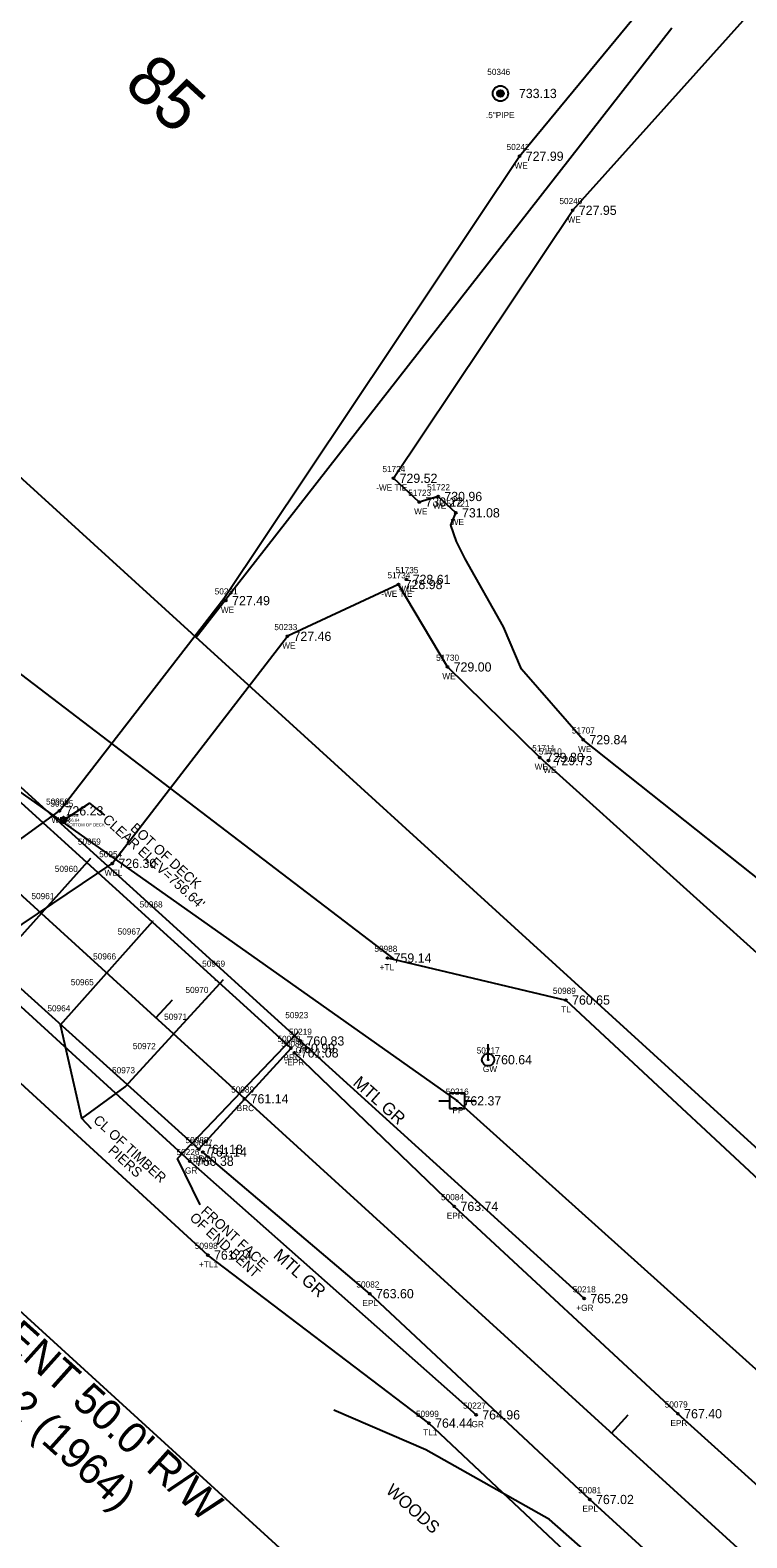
# Model space of a CAD drawing. Extents: x 1378245 to 1381654, y 996521 to 1000567.
# Drawn here: x 1379687.6 to 1379803.9, y 998853.4 to 999097.9 of the extents above; entities that cross this region are included whole.
import ezdxf

# ---------------------------------------------------------------- set-up
doc = ezdxf.new("R2010")
doc.units = 0
for name, color, linetype in [('Default', 7, 'Continuous'), ('RD_EX_Bridge', 7, 'Continuous'), ('RD_EX_Bridge_txCode', 7, 'Continuous'), ('RD_EX_DV_Prop', 7, 'Continuous'), ('RD_EX_DV_Prop_txCode', 7, 'Continuous'), ('RD_EX_DV_PropPin', 7, 'Continuous'), ('RD_EX_GuardRail', 7, 'Continuous'), ('RD_EX_GuardRail_txCode', 7, 'Continuous'), ('RD_EX_H2O', 7, 'Continuous'), ('RD_EX_H2O_txCode', 7, 'Continuous'), ('RD_EX_Road', 7, 'Continuous'), ('RD_EX_Road_txCode', 7, 'Continuous'), ('RD_EX_RW', 7, 'Continuous'), ('RD_EX_RW_TX', 7, 'Continuous'), ('RD_EX_SU_Elec', 7, 'Continuous'), ('RD_EX_TX_Bridge_ELEV', 7, 'Continuous'), ('RD_EX_TX_DV_Prop_ELEV', 7, 'Continuous'), ('RD_EX_TX_GuardRail_ELEV', 7, 'Continuous'), ('RD_EX_TX_H2O_ELEV', 7, 'Continuous'), ('RD_EX_TX_Road_ELEV', 7, 'Continuous'), ('RD_EX_TX_UT_ELEV', 7, 'Continuous'), ('RD_EX_TX_VEG_ELEV', 7, 'Continuous'), ('RD_EX_UT', 7, 'Continuous'), ('RD_EX_UT_txCode', 7, 'Continuous'), ('RD_EX_VEG', 7, 'Continuous'), ('RD_EX_VEG_txCode', 7, 'Continuous'), ('RD_HC_Cl', 7, 'Continuous'), ('RD_HC_Data_Tic', 7, 'Continuous'), ('RD_HC_Survey_ELEV', 7, 'Continuous'), ('RD_HC_TX_Sta50', 7, 'Continuous'), ('RD_SMD_Locator', 7, 'Continuous'), ('RD_TX_Misc1', 7, 'Continuous'), ('RD_TX_Misc2', 7, 'Continuous')]:
    doc.layers.add(name, color=color, linetype=linetype)

msp = doc.modelspace()

# ---------------------------------------------------------------- linework, layer by layer
at = {"layer": 'Default'}
for p, q in [((1379693.05, 998969.77), (1379693.03, 998969.77)), ((1379693.04, 998969.78), (1379693.04, 998969.76)), ((1379697.51, 998963.6), (1379697.49, 998963.6)), ((1379697.5, 998963.61), (1379697.5, 998963.59)), ((1379693.83, 998959.18), (1379693.81, 998959.18)), ((1379693.82, 998959.19), (1379693.82, 998959.17)), ((1379689.7, 998954.76), (1379689.7, 998954.75)), ((1379689.71, 998954.76), (1379689.7, 998954.76)), ((1379707.56, 998953.42), (1379707.55, 998953.42)), ((1379707.56, 998953.43), (1379707.56, 998953.42)), ((1379703.98, 998949.01), (1379703.96, 998949.01)), ((1379703.97, 998949.02), (1379703.97, 998949)), ((1379700.03, 998944.98), (1379700.01, 998944.98)), ((1379700.02, 998944.99), (1379700.02, 998944.97)), ((1379717.7, 998943.8), (1379717.68, 998943.8)), ((1379717.69, 998943.81), (1379717.69, 998943.79)), ((1379696.39, 998940.8), (1379696.37, 998940.8)), ((1379696.38, 998940.81), (1379696.38, 998940.79)), ((1379715.01, 998939.54), (1379714.99, 998939.54)), ((1379715, 998939.55), (1379715, 998939.53)), ((1379692.59, 998936.56), (1379692.57, 998936.56)), ((1379692.58, 998936.57), (1379692.58, 998936.55)), ((1379711.22, 998935.19), (1379711.2, 998935.19)), ((1379711.21, 998935.2), (1379711.21, 998935.18)), ((1379731.16, 998935.46), (1379731.14, 998935.46)), ((1379731.15, 998935.46), (1379731.15, 998935.45)), ((1379706.43, 998930.43), (1379706.41, 998930.43)), ((1379706.42, 998930.44), (1379706.42, 998930.43)), ((1379703.04, 998926.52), (1379703.04, 998926.5)), ((1379703.05, 998926.51), (1379703.04, 998926.51))]:
    msp.add_line(p, q, dxfattribs=at)
msp.add_lwpolyline([(1379692.44, 998969.77), (1379693.64, 998969.77), (1379693.04, 998969.77), (1379693.04, 998970.37), (1379693.04, 998969.17)], dxfattribs=at)
msp.add_circle((1379693.04, 998969.77), 0.469, dxfattribs=at)
at = {"layer": 'RD_EX_Bridge'}
for p, q in [((1379681.87, 998946.21), (1379697.5, 998963.6)), ((1379692.58, 998936.56), (1379707.56, 998953.42)), ((1379703.04, 998926.51), (1379719.03, 998943.94)), ((1379711.57, 998914.92), (1379731.15, 998935.46))]:
    msp.add_line(p, q, dxfattribs=at)
msp.add_lwpolyline([(1379715.01, 998916.39), (1379729.96, 998932.8), (1379652.41, 999003.17), (1379637.22, 998986.55), (1379715.01, 998916.39)], dxfattribs=at)
at = {"layer": 'RD_EX_DV_Prop'}
msp.add_line((1379791.75, 999098.24), (1379714.55, 998999.4), dxfattribs=at)
at = {"layer": 'RD_EX_DV_PropPin'}
for p, q in [((1379763.42, 999087.51), (1379763.42, 999087.79)), ((1379763.44, 999087.44), (1379763.44, 999087.86)), ((1379763.47, 999087.38), (1379763.47, 999087.91)), ((1379763.49, 999087.34), (1379763.49, 999087.95)), ((1379763.52, 999087.31), (1379763.52, 999087.99)), ((1379763.54, 999087.28), (1379763.54, 999088.02)), ((1379763.57, 999087.25), (1379763.57, 999088.04)), ((1379763.59, 999087.23), (1379763.59, 999088.06)), ((1379763.62, 999087.21), (1379763.62, 999088.08)), ((1379763.64, 999087.19), (1379763.64, 999088.1)), ((1379763.67, 999087.18), (1379763.67, 999088.12)), ((1379763.69, 999087.17), (1379763.69, 999088.13)), ((1379763.72, 999087.15), (1379763.72, 999088.14)), ((1379763.74, 999087.14), (1379763.74, 999088.15)), ((1379763.77, 999087.13), (1379763.77, 999088.16)), ((1379763.79, 999087.13), (1379763.79, 999088.17)), ((1379763.82, 999087.12), (1379763.82, 999088.18)), ((1379763.84, 999087.11), (1379763.84, 999088.18)), ((1379763.87, 999087.11), (1379763.87, 999088.19)), ((1379763.89, 999087.11), (1379763.89, 999088.19)), ((1379763.92, 999087.11), (1379763.92, 999088.19)), ((1379763.94, 999087.1), (1379763.94, 999088.19)), ((1379763.97, 999087.11), (1379763.97, 999088.19)), ((1379763.99, 999087.11), (1379763.99, 999088.19)), ((1379764.02, 999087.11), (1379764.02, 999088.19)), ((1379764.04, 999087.11), (1379764.04, 999088.18)), ((1379764.07, 999087.12), (1379764.07, 999088.18)), ((1379764.09, 999087.13), (1379764.09, 999088.17)), ((1379764.12, 999087.13), (1379764.12, 999088.16)), ((1379764.14, 999087.14), (1379764.14, 999088.15)), ((1379764.17, 999087.15), (1379764.17, 999088.14)), ((1379764.19, 999087.17), (1379764.19, 999088.13)), ((1379764.22, 999087.18), (1379764.22, 999088.12)), ((1379764.24, 999087.19), (1379764.24, 999088.1)), ((1379764.27, 999087.21), (1379764.27, 999088.08)), ((1379764.29, 999087.23), (1379764.29, 999088.06)), ((1379764.32, 999087.25), (1379764.32, 999088.04)), ((1379764.34, 999087.28), (1379764.34, 999088.02)), ((1379764.37, 999087.31), (1379764.37, 999087.99)), ((1379764.39, 999087.34), (1379764.39, 999087.95)), ((1379764.42, 999087.38), (1379764.42, 999087.91)), ((1379764.44, 999087.44), (1379764.44, 999087.86)), ((1379764.47, 999087.51), (1379764.47, 999087.79))]:
    msp.add_line(p, q, dxfattribs=at)
for radius in [1.25, 0.543]:
    msp.add_circle((1379763.94, 999087.65), radius, dxfattribs=at)
at = {"layer": 'RD_EX_GuardRail'}
for points in [[(1379497.52, 999109.58), (1379635.64, 998985.68), (1379713.53, 998914.45), (1379759.99, 998873.32)], [(1379777.52, 998892.18), (1379731.47, 998933.97), (1379653.8, 999004.42), (1379553.93, 999097.04)]]:
    msp.add_lwpolyline(points, dxfattribs=at)
at = {"layer": 'RD_EX_H2O'}
for points in [[(1379663.75, 998950.52), (1379692.38, 998971.29), (1379719.04, 999005.74), (1379767.05, 999077.47), (1379820.32, 999142.06), (1379856.78, 999184.17), (1379909.65, 999199.37), (1379968.41, 999216.31), (1380029.43, 999227.41), (1380049.41, 999276.13), (1380067, 999316.44)], [(1379746.58, 999025.23), (1379775.66, 999068.7), (1379833.36, 999132.97), (1379865.6, 999174.54), (1379921.65, 999184.16), (1379977.93, 999198.09), (1380034.4, 999218.74), (1380062.36, 999262.9), (1380081.88, 999311.7)], [(1379756.7, 999019.63), (1379753.84, 999022.28), (1379750.77, 999021.38), (1379746.58, 999025.23)], [(1379918.79, 998846.24), (1379910.28, 998856.59), (1379904.93, 998863.62), (1379897.77, 998868.2), (1379895.82, 998874.91), (1379890.92, 998880.91), (1379881.01, 998897.71), (1379867.05, 998914.16), (1379841.93, 998934), (1379817.55, 998950.92), (1379777.38, 998982.83), (1379767.36, 998994.27), (1379764.43, 999001.11), (1379758.21, 999012.18), (1379756.79, 999014.96), (1379755.88, 999017.65), (1379756.7, 999019.63)], [(1379901.08, 998848.93), (1379897.44, 998858.7), (1379895.56, 998859.46), (1379891.1, 998862.46), (1379885.95, 998867.36), (1379882.04, 998876.42), (1379877.1, 998894.85), (1379861.31, 998910.26), (1379835.53, 998927.59), (1379812.63, 998941.87), (1379770.33, 998979.95), (1379755.35, 998994.63), (1379747.4, 999008), (1379729.37, 998999.6)], [(1379671.83, 998943.2), (1379700.96, 998962.76), (1379729.37, 998999.6)], [(1380261.25, 998409.34), (1380207.72, 998459.99), (1380160.95, 998503.9), (1380116.04, 998544.61), (1380073.47, 998582.91), (1380032.2, 998621.67), (1379983.75, 998664.27), (1379936.35, 998705.94), (1379893.4, 998746.57), (1379847.09, 998789.13), (1379801.41, 998830.34), (1379771.89, 998856.37), (1379751.83, 998867.64), (1379736.89, 998874.07)]]:
    msp.add_lwpolyline(points, dxfattribs=at)
at = {"layer": 'RD_EX_Road'}
for points in [[(1380011.64, 998674.46), (1379968.26, 998714.25), (1379924.81, 998753.18), (1379879.74, 998794.22), (1379836.83, 998833.73), (1379792.75, 998873.5), (1379756.46, 998907.13), (1379730.54, 998932.03)], [(1379997.47, 998660), (1379953.44, 998699.92), (1379910.65, 998738.56), (1379864.96, 998780.17), (1379823.13, 998818.8), (1379778.45, 998859.59), (1379742.74, 998892.97), (1379715.65, 998915.95)]]:
    msp.add_lwpolyline(points, dxfattribs=at)
at = {"layer": 'RD_EX_RW'}
for p, q in [((1379446.02, 999244.05), (1379815.63, 998907.31)), ((1379378.68, 999170.13), (1379748.28, 998833.39))]:
    msp.add_line(p, q, dxfattribs=at)
at = {"layer": 'RD_EX_SU_Elec'}
msp.add_lwpolyline([(1378514.25, 999944.12), (1378777.7, 999831.22), (1379190.17, 999461.05), (1379403.33, 999174.04), (1379756.94, 998924.25), (1380051.16, 998659.97), (1380327.91, 998390.65), (1380546.23, 998058.37)], dxfattribs=at)
at = {"layer": 'RD_EX_UT'}
for p, q in [((1379761.93, 998930.92), (1379761.93, 998933.42)), ((1379758.18, 998925.51), (1379755.68, 998925.51)), ((1379755.68, 998925.51), (1379755.68, 998923.01)), ((1379758.18, 998923.01), (1379758.18, 998925.51)), ((1379753.97, 998924.23), (1379755.7, 998924.23)), ((1379755.68, 998923.01), (1379758.18, 998923.01)), ((1379758.15, 998924.23), (1379759.97, 998924.23))]:
    msp.add_line(p, q, dxfattribs=at)
msp.add_circle((1379761.93, 998930.92), 1, dxfattribs=at)
at = {"layer": 'RD_EX_VEG'}
for p, q in [((1379635.72, 999031.86), (1379746.57, 998947.26)), ((1379716.47, 998899.23), (1379620.44, 998987.26))]:
    msp.add_line(p, q, dxfattribs=at)
for points in [[(1379745.61, 998947.42), (1379774.57, 998940.6), (1379816.01, 998901.98), (1379842.25, 998875.07), (1379890.91, 998833.28), (1379928.8, 998787.62), (1379978.22, 998752.26), (1380041.75, 998705.92), (1380067.2, 998663.35), (1380118.8, 998637.22), (1380159.3, 998606.26), (1380204.39, 998555.8), (1380215.44, 998549.46)], [(1380572.26, 997755.47), (1380563.06, 997802.88), (1380548.57, 997859.96), (1380528.6, 997926.15), (1380512.76, 997988.52), (1380488.02, 998054.97), (1380458.55, 998120.18), (1380432.73, 998176.36), (1380395.75, 998235.49), (1380345.67, 998286.69), (1380306.05, 998354.38), (1380256.57, 998407.41), (1380203.97, 998456.66), (1380158.7, 998500.55), (1380112.46, 998542.96), (1380070.42, 998580.38), (1380028.44, 998619.77), (1379982.76, 998660.07), (1379934.04, 998703.39), (1379891.18, 998743.94), (1379841.91, 998788.98), (1379798.41, 998828.62), (1379752.34, 998871.98), (1379716.47, 998899.23)]]:
    msp.add_lwpolyline(points, dxfattribs=at)
at = {"layer": 'RD_HC_Cl'}
msp.add_line((1378781.54, 999781.8), (1380217.09, 998473.92), dxfattribs=at)
at = {"layer": 'RD_HC_Data_Tic'}
for p, q in [((1379708.03, 998937.7), (1379710.73, 998940.66)), ((1379781.96, 998870.35), (1379784.65, 998873.31))]:
    msp.add_line(p, q, dxfattribs=at)
at = {"layer": 'RD_SMD_Locator'}
for centre, radius in [((1379763.94, 999087.65), 0.075), ((1379767.05, 999077.47), 0.15), ((1379775.66, 999068.7), 0.15), ((1379746.58, 999025.23), 0.15), ((1379750.77, 999021.38), 0.15), ((1379753.84, 999022.28), 0.15), ((1379756.7, 999019.63), 0.15), ((1379747.4, 999008), 0.15), ((1379748.7, 999008.83), 0.15), ((1379719.41, 999005.39), 0.15), ((1379729.37, 998999.6), 0.15), ((1379755.35, 998994.63), 0.15), ((1379777.38, 998982.83), 0.15), ((1379770.33, 998979.95), 0.15), ((1379771.73, 998979.43), 0.15), ((1379692.38, 998971.29), 0.15), ((1379700.96, 998962.76), 0.15), ((1379745.61, 998947.42), 0.15), ((1379774.57, 998940.6), 0.15), ((1379729.96, 998932.8), 0.15), ((1379730.54, 998932.03), 0.15), ((1379731.47, 998933.97), 0.15), ((1379761.93, 998930.92), 0.075), ((1379722.41, 998924.58), 0.15), ((1379756.94, 998924.25), 0.075), ((1379715.01, 998916.39), 0.15), ((1379715.65, 998915.95), 0.15), ((1379713.53, 998914.45), 0.15), ((1379756.46, 998907.13), 0.15), ((1379716.47, 998899.23), 0.15), ((1379742.74, 998892.97), 0.15), ((1379777.52, 998892.18), 0.15), ((1379759.99, 998873.32), 0.15), ((1379792.75, 998873.5), 0.15), ((1379752.34, 998871.98), 0.15), ((1379778.45, 998859.59), 0.15)]:
    msp.add_circle(centre, radius, dxfattribs=at)
at = {"layer": 'RD_TX_Misc1'}
for p, q in [((1379696.04, 998921.41), (1379692.58, 998936.56)), ((1379715.22, 998907.36), (1379711.57, 998914.92))]:
    msp.add_line(p, q, dxfattribs=at)
msp.add_lwpolyline([(1379693.04, 998969.77), (1379697.26, 998972.56), (1379699.72, 998970.59)], dxfattribs=at)
msp.add_circle((1379693.04, 998969.77), 0.466, dxfattribs=at)
at = {"layer": 'RD_TX_Misc2'}
msp.add_lwpolyline([(1379697.61, 998919.72), (1379696.04, 998921.41), (1379703.04, 998926.51)], dxfattribs=at)

# ---------------------------------------------------------------- texts
at = {"layer": 'Default'}
for s, height, p in [('50925', 1, (1379690.92, 998971.97)), ('50925', 0.5, (1379693.54, 998970.27)), ('756.64', 0.5, (1379693.54, 998969.52)), ('BOTTOM OF DECK', 0.5, (1379693.54, 998968.77)), ('50959', 1, (1379695.38, 998965.8)), ('50960', 1, (1379691.64, 998961.38)), ('50961', 1, (1379687.85, 998956.96)), ('50968', 1, (1379705.41, 998955.62)), ('50967', 1, (1379701.83, 998951.21)), ('50966', 1, (1379697.86, 998947.18)), ('50969', 1, (1379715.55, 998946)), ('50965', 1, (1379694.24, 998943)), ('50970', 1, (1379712.84, 998941.74)), ('50964', 1, (1379690.44, 998938.76)), ('50971', 1, (1379709.38, 998937.39)), ('50923', 1, (1379729.03, 998937.66)), ('50972', 1, (1379704.3, 998932.63)), ('50973', 1, (1379700.93, 998928.71))]:
    msp.add_text(s, height=height, dxfattribs=at).set_placement(p)
at = {"layer": 'RD_EX_Bridge_txCode'}
for s, p in [('50090', (1379727.77, 998933.8)), ('-BRC', (1379728.3, 998930.8)), ('50089', (1379720.25, 998925.58)), ('BRC', (1379721.15, 998922.58)), ('50088', (1379712.85, 998917.39)), ('+BRC', (1379713.27, 998914.39))]:
    msp.add_text(s, height=1, dxfattribs=at).set_placement(p)
at = {"layer": 'RD_EX_DV_Prop_txCode'}
for s, p in [('50346', (1379761.8, 999090.65)), ('.5"PIPE', (1379761.59, 999083.65))]:
    msp.add_text(s, height=1, dxfattribs=at).set_placement(p)
at = {"layer": 'RD_EX_GuardRail_txCode'}
for s, p in [('50219', (1379729.63, 998934.97)), ('GR', (1379730.69, 998931.97)), ('50226', (1379711.39, 998915.45)), ('GR', (1379712.75, 998912.45)), ('50218', (1379775.68, 998893.18)), ('+GR', (1379776.25, 998890.18)), ('50227', (1379757.87, 998874.32)), ('-GR', (1379758.8, 998871.32))]:
    msp.add_text(s, height=1, dxfattribs=at).set_placement(p)
at = {"layer": 'RD_EX_H2O_txCode'}
for s, p in [('50242', (1379764.94, 999078.47)), ('WE', (1379766.22, 999075.47)), ('50240', (1379773.51, 999069.7)), ('WE', (1379774.82, 999066.7)), ('51724', (1379744.79, 999026.23)), ('-WE TIE', (1379743.78, 999023.23)), ('51723', (1379748.98, 999022.38)), ('51722', (1379752.04, 999023.28)), ('WE', (1379749.93, 999019.38)), ('WE', (1379753, 999020.28)), ('51721', (1379755.19, 999020.63)), ('WE', (1379755.87, 999017.63)), ('51735', (1379746.91, 999009.83)), ('51734', (1379745.61, 999009)), ('50231', (1379717.58, 999006.39)), ('-WE TIE', (1379744.6, 999006)), ('-WE', (1379747.45, 999006.83)), ('WE', (1379718.58, 999003.39)), ('50233', (1379727.26, 999000.6)), ('WE', (1379728.54, 998997.6)), ('51730', (1379753.51, 998995.63)), ('WE', (1379754.51, 998992.63)), ('51707', (1379775.54, 998983.83)), ('51711', (1379769.1, 998980.95)), ('51710', (1379770.18, 998980.43)), ('WE', (1379776.54, 998980.83)), ('WE', (1379769.49, 998977.95)), ('WE', (1379770.89, 998977.43)), ('50950', (1379690.22, 998972.29)), ('WER', (1379691.09, 998969.29)), ('50954', (1379698.84, 998963.76)), ('WEL', (1379699.7, 998960.76))]:
    msp.add_text(s, height=1, dxfattribs=at).set_placement(p)
at = {"layer": 'RD_EX_Road_txCode'}
for s, p in [('50085', (1379728.38, 998933.03)), ('-EPR', (1379728.9, 998930.03)), ('50087', (1379713.49, 998916.95)), ('-EPL', (1379714.03, 998913.95)), ('50084', (1379754.3, 998908.13)), ('EPR', (1379755.23, 998905.13)), ('50082', (1379740.58, 998893.97)), ('EPL', (1379741.54, 998890.97)), ('50079', (1379790.6, 998874.5)), ('EPR', (1379791.53, 998871.5)), ('50081', (1379776.57, 998860.59)), ('EPL', (1379777.24, 998857.59))]:
    msp.add_text(s, height=1, dxfattribs=at).set_placement(p)
at = {"layer": 'RD_EX_RW_TX'}
for s, p in [("PRESENT 50.0' R/W", (1379669.33, 998897.54)), ('37.522 (1964)', (1379670.97, 998885.33))]:
    msp.add_text(s, height=5, rotation=318.1047, dxfattribs=at).set_placement(p)
at = {"layer": 'RD_EX_TX_Bridge_ELEV'}
for s, p in [('760.99', (1379730.96, 998932.05)), ('761.14', (1379723.41, 998923.83)), ('761.18', (1379716.01, 998915.64))]:
    msp.add_text(s, height=1.5, dxfattribs=at).set_placement(p)
at = {"layer": 'RD_EX_TX_DV_Prop_ELEV'}
msp.add_text('733.13', height=1.5, dxfattribs=at).set_placement((1379766.94, 999086.9))
at = {"layer": 'RD_EX_TX_GuardRail_ELEV'}
for s, p in [('760.83', (1379732.47, 998933.22)), ('760.38', (1379714.53, 998913.7)), ('765.29', (1379778.52, 998891.43)), ('764.96', (1379760.99, 998872.57))]:
    msp.add_text(s, height=1.5, dxfattribs=at).set_placement(p)
at = {"layer": 'RD_EX_TX_H2O_ELEV'}
for s, p in [('727.99', (1379768.05, 999076.72)), ('727.95', (1379776.66, 999067.95)), ('729.52', (1379747.58, 999024.48)), ('730.96', (1379754.84, 999021.53)), ('730.22', (1379751.77, 999020.63)), ('731.08', (1379757.7, 999018.88)), ('728.98', (1379748.4, 999007.25)), ('728.61', (1379749.7, 999008.08)), ('727.49', (1379720.41, 999004.64)), ('727.46', (1379730.37, 998998.85)), ('729.00', (1379756.35, 998993.88)), ('729.84', (1379778.38, 998982.08)), ('729.80', (1379771.33, 998979.2)), ('729.73', (1379772.73, 998978.68)), ('726.23', (1379693.38, 998970.54)), ('726.30', (1379701.96, 998962.01))]:
    msp.add_text(s, height=1.5, dxfattribs=at).set_placement(p)
at = {"layer": 'RD_EX_TX_Road_ELEV'}
for s, p in [('761.08', (1379731.54, 998931.28)), ('761.14', (1379716.65, 998915.2)), ('763.74', (1379757.46, 998906.38)), ('763.60', (1379743.74, 998892.22)), ('767.40', (1379793.75, 998872.75)), ('767.02', (1379779.45, 998858.84))]:
    msp.add_text(s, height=1.5, dxfattribs=at).set_placement(p)
at = {"layer": 'RD_EX_TX_UT_ELEV'}
msp.add_text('760.64', height=1.5, dxfattribs=at).set_placement((1379762.93, 998930.17))
at = {"layer": 'RD_EX_TX_VEG_ELEV'}
for s, p in [('759.14', (1379746.61, 998946.67)), ('760.65', (1379775.57, 998939.85)), ('761.24', (1379717.47, 998898.48)), ('764.44', (1379753.34, 998871.23))]:
    msp.add_text(s, height=1.5, dxfattribs=at).set_placement(p)
at = {"layer": 'RD_EX_UT_txCode'}
for s, p in [('50217', (1379760.09, 998931.92)), ('GW', (1379761.09, 998928.92)), ('50216', (1379755.08, 998925.25)), ('PP', (1379756.16, 998922.25))]:
    msp.add_text(s, height=1, dxfattribs=at).set_placement(p)
at = {"layer": 'RD_EX_VEG_txCode'}
for s, p in [('50988', (1379743.49, 998948.42)), ('+TL', (1379744.35, 998945.42)), ('50989', (1379772.45, 998941.6)), ('TL', (1379773.8, 998938.6)), ('50998', (1379714.35, 998900.23)), ('+TL1', (1379715.04, 998897.23)), ('50999', (1379750.23, 998872.98)), ('TL1', (1379751.41, 998869.98))]:
    msp.add_text(s, height=1, dxfattribs=at).set_placement(p)
at = {"layer": 'RD_HC_Survey_ELEV'}
msp.add_text('762.37', height=1.5, dxfattribs=at).set_placement((1379757.94, 998923.5))
at = {"layer": 'RD_HC_TX_Sta50'}
msp.add_text('85', height=8, rotation=317.6642, dxfattribs=at).set_placement((1379702.59, 999088.76))
at = {"layer": 'RD_TX_Misc1'}
for s, p in [("CLEAR ELEV=756.64'", (1379699.28, 998969.69)), ('BOT OF DECK', (1379703.77, 998968.3)), ('CL OF TIMBER', (1379697.76, 998920.92)), (' PIERS', (1379699.73, 998916.42)), ('OF END BENT', (1379713.4, 998905.11)), ('FRONT FACE', (1379715.22, 998906.16))]:
    msp.add_text(s, height=1.6, rotation=317.6383, dxfattribs=at).set_placement(p)
at = {"layer": 'RD_TX_Misc2'}
for s, rotation, p in [('MTL GR', 318.2461, (1379739.87, 998926.95)), ('MTL GR', 318.2461, (1379726.95, 998898.96)), ('WOODS', 318.3448, (1379745.21, 998860.82))]:
    msp.add_text(s, height=2, rotation=rotation, dxfattribs=at).set_placement(p)

doc.saveas('drawing.dxf')
